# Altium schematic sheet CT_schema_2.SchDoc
size 212 x 203 mm
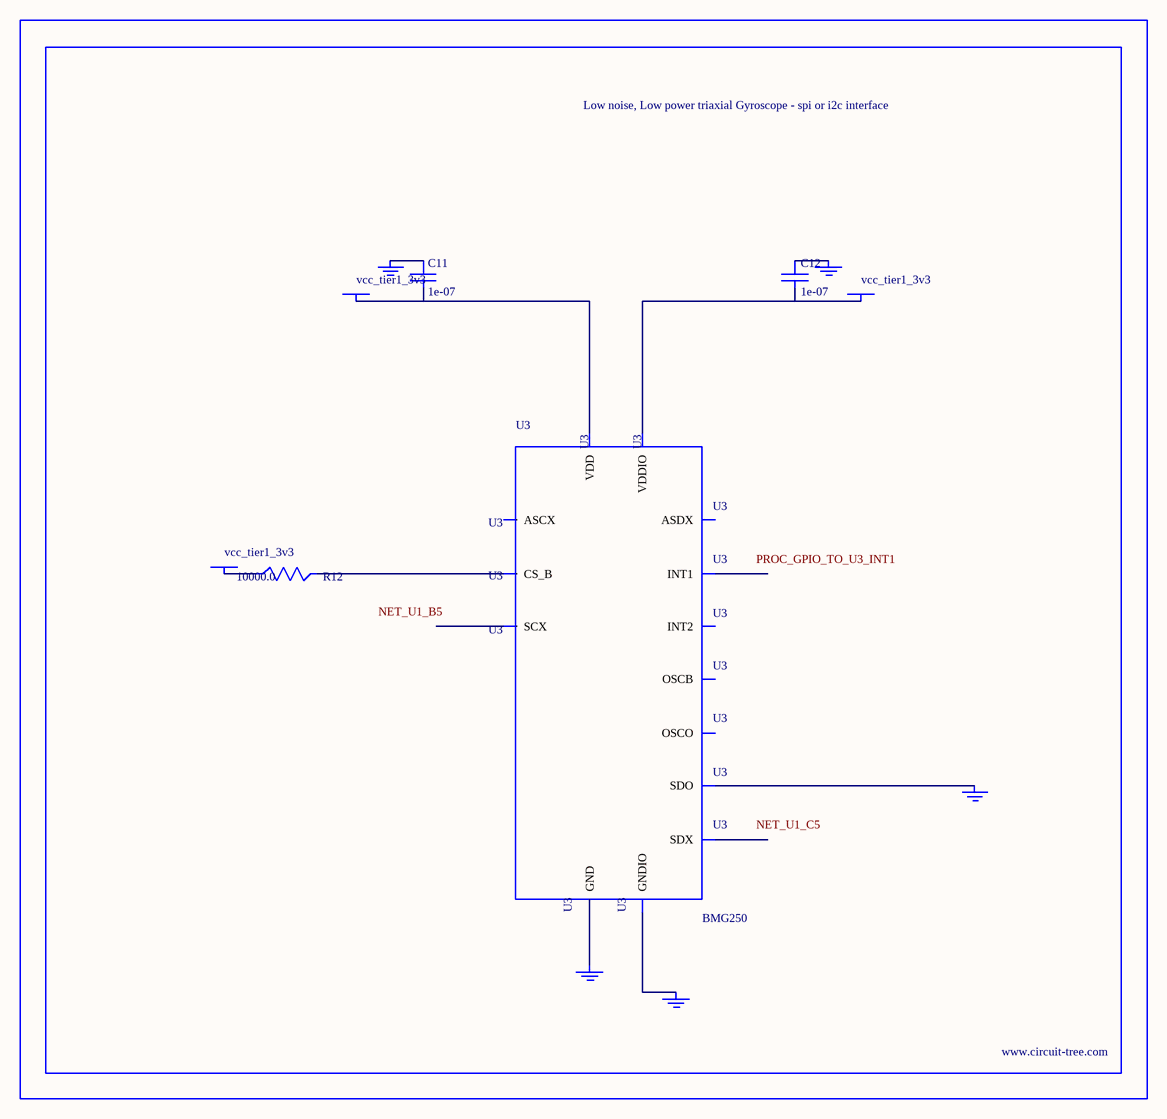
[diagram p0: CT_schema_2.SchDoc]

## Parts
BORDER1  (no value)
C11  1e-07  [C0402]
C12  1e-07  [C0402]
GND_INSTANCE_1_0  (no value)
GND_INSTANCE_1_1  (no value)
GND_INSTANCE_1_2  (no value)
GND_INSTANCE_1_3  (no value)
GND_INSTANCE_1_4  (no value)
POWER_INSTANCE_1_0  vcc_tier1_3v3
POWER_INSTANCE_1_1  vcc_tier1_3v3
POWER_INSTANCE_1_2  vcc_tier1_3v3
R12  10000.0  [R0603]
U3  BMG250  [LGA-14]

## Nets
NetC11_1: C11.1 GND_INSTANCE_1_3.0(GND)
NetC11_2: C11.2 POWER_INSTANCE_1_1.0(PWR) U3.8(VDD)
NetC12_1: C12.1 GND_INSTANCE_1_1.0(GND)
NetC12_2: C12.2 POWER_INSTANCE_1_0.0(PWR) U3.5(VDDIO)
NetGND_INSTANCE_1_0_0: GND_INSTANCE_1_0.0(GND) U3.1(SDO)
NetGND_INSTANCE_1_2_0: GND_INSTANCE_1_2.0(GND) U3.6(GNDIO)
NetGND_INSTANCE_1_4_0: GND_INSTANCE_1_4.0(GND) U3.7(GND)
NetPOWER_INSTANCE_1_2_0: POWER_INSTANCE_1_2.0(PWR) R12.1
NetR12_2: R12.2 U3.12(CS_B)

Not connected (* = marked no-connect by the designer): U3 2(ASDX) 3(ASCX) 4(INT1) 9(INT2) 10(OSCB) 11(OSCO) 13(SCX) 14(SDX)

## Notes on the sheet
- Labels drawn without touching a wire or pin: NET_U1_B5, NET_U1_C5, PROC_GPIO_TO_U3_INT1

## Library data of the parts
BORDER1 = BORDER_PAGE1
C11 C12 = C0402C104K3RACTU
GND_INSTANCE_1_0-GND_INSTANCE_1_4 = GND
POWER_INSTANCE_1_0-POWER_INSTANCE_1_2 = PWR
R12 = RC0603JR-0710KL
